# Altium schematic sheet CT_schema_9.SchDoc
size 278 x 170 mm
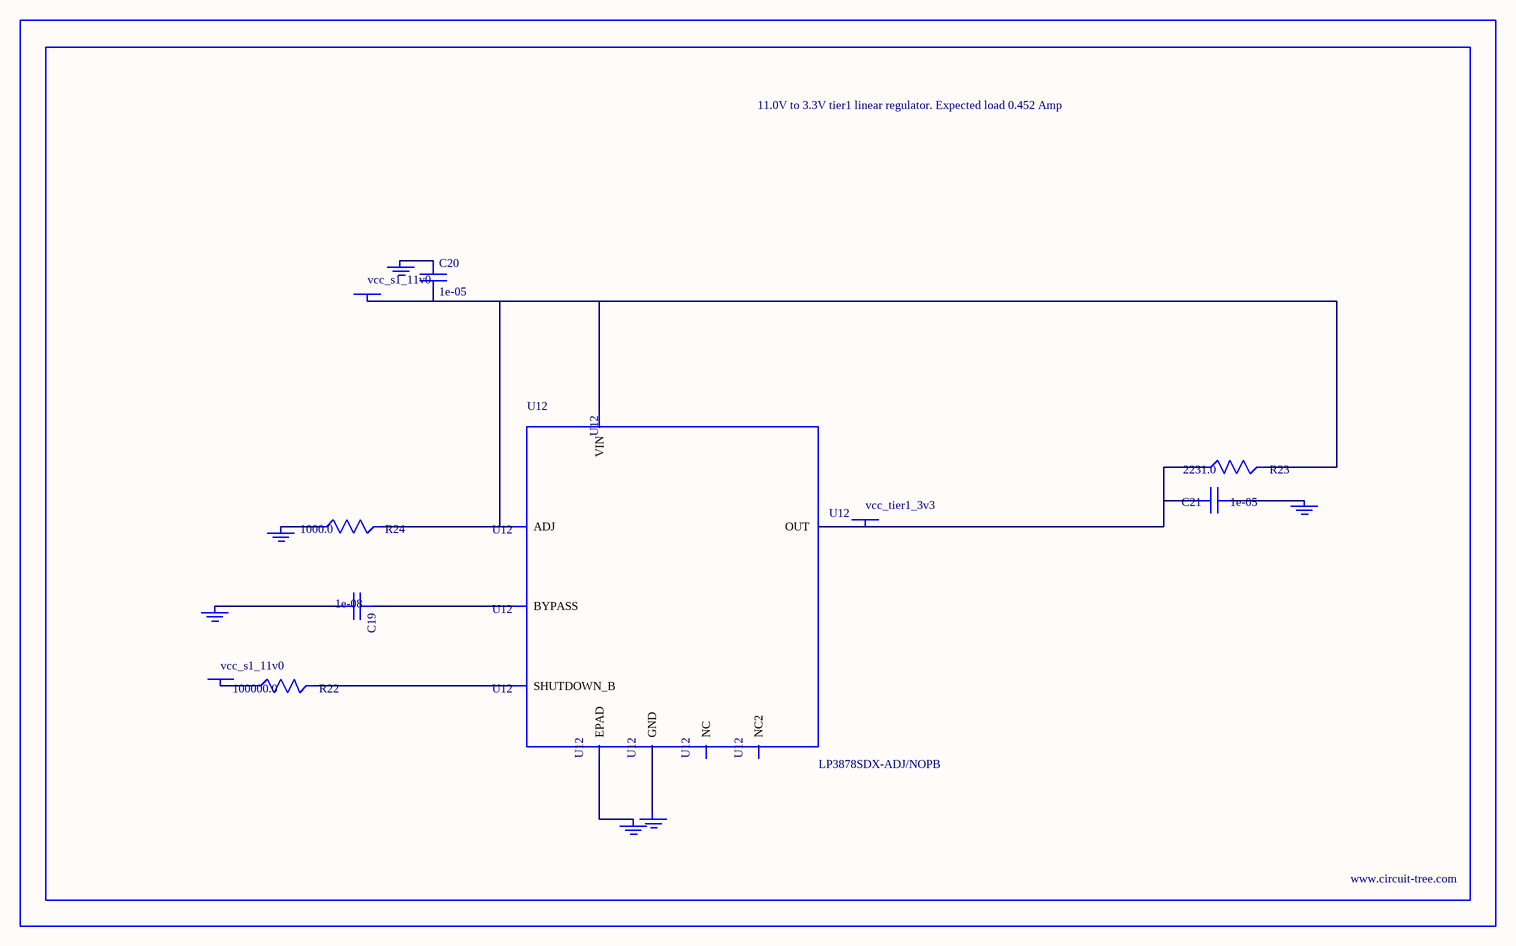
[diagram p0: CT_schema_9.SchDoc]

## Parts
BORDER8  (no value)
C19  1e-08  [C0402]
C20  1e-05  [C1206]
C21  1e-05  [C1210]
GND_INSTANCE_8_0  (no value)
GND_INSTANCE_8_1  (no value)
GND_INSTANCE_8_2  (no value)
GND_INSTANCE_8_3  (no value)
GND_INSTANCE_8_4  (no value)
GND_INSTANCE_8_5  (no value)
POWER_INSTANCE_8_0  vcc_s1_11v0
POWER_INSTANCE_8_1  vcc_s1_11v0
POWER_INSTANCE_8_2  vcc_tier1_3v3
R22  100000.0  [R0603]
R23  2231.0  [R0603]
R24  1000.0  [R0603]
U12  LP3878SDX-ADJ/NOPB  [WSON-8]

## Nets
NetC19_1: C19.1 U12.1(BYPASS)
NetC19_2: C19.2 GND_INSTANCE_8_0.0(GND)
NetC20_1: C20.1 GND_INSTANCE_8_1.0(GND)
NetC20_2: C20.2 POWER_INSTANCE_8_0.0(PWR) R23.2 R24.2 U12.4(VIN) U12.6(ADJ)
NetC21_1: C21.1 GND_INSTANCE_8_2.0(GND)
NetC21_2: C21.2 POWER_INSTANCE_8_2.0(PWR) R23.1 U12.5(OUT)
NetGND_INSTANCE_8_3_0: GND_INSTANCE_8_3.0(GND) R24.1
NetGND_INSTANCE_8_4_0: GND_INSTANCE_8_4.0(GND) U12.PAD(EPAD)
NetGND_INSTANCE_8_5_0: GND_INSTANCE_8_5.0(GND) U12.3(GND)
NetPOWER_INSTANCE_8_1_0: POWER_INSTANCE_8_1.0(PWR) R22.1
NetR22_2: R22.2 U12.8(SHUTDOWN_B)

Not connected (* = marked no-connect by the designer): U12 2(NC) 7(NC2)

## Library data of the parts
BORDER8 = BORDER_PAGE8
C19 = C0402C103K3RAC
C20 = C1206C106K3RACTU
C21 = GRM32DR61E106MA12L
GND_INSTANCE_8_0-GND_INSTANCE_8_5 = GND
POWER_INSTANCE_8_0-POWER_INSTANCE_8_2 = PWR
R22 = RC0603JR-07100KL
R23 = R23
R24 = RC0603JR-071KL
